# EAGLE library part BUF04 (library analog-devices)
Closed-Loop High Speed Buffer OBSOLETE Source: http://www.analog.com/static/imported-files/data_sheets_obsolete/820549BUF04.pdf
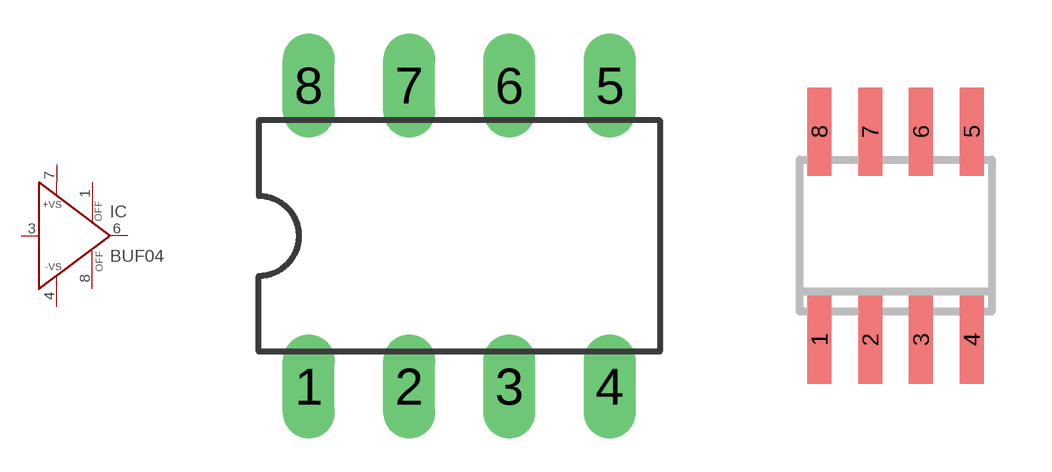
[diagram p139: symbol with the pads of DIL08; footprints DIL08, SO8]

Designator prefix IC

## BUF04P (OC_FARNELL: unknown; OC_NEWARK: unknown)  [DIL08]
1  OFF  pas
3  IN  in
4  -VS  in
6  OUT  out
7  +VS  in
8  OFF  pas

## BUF04S (OC_FARNELL: unknown; OC_NEWARK: unknown)  [SO8]
Pads as for DIL08

## Footprint DIL08 (pad centres in mm)
Dual In Line Package
drill 0.813 long: 1 -3.81,-3.81; 2 -1.27,-3.81; 3 1.27,-3.81; 4 3.81,-3.81; 5 3.81,3.81; 6 1.27,3.81; 7 -1.27,3.81; 8 -3.81,3.81

## Footprint SO8 (pad centres in mm)
8-Lead Small Outline IC (SO-8) Source: http://www.analog.com/UploadedFiles/Data_Sheets/703465986AD8611_2_0.pdf
smd 0.6 x 2.2: 1 -1.905,-2.6; 2 -0.635,-2.6; 3 0.635,-2.6; 4 1.905,-2.6; 5 1.905,2.6; 6 0.635,2.6; 7 -0.635,2.6; 8 -1.905,2.6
